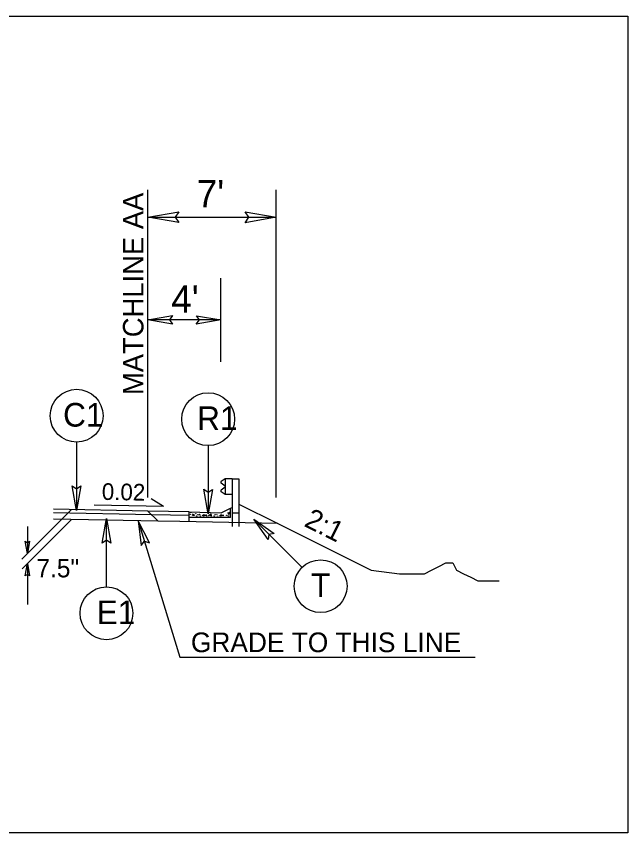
# Model space of a CAD drawing. Extents: x 1818040 to 1825768, y 638918 to 648046.
# Drawn here: x 1819386 to 1819887, y 645663 to 646332 of the extents above; entities that cross this region are included whole.
import ezdxf

# ---------------------------------------------------------------- set-up
doc = ezdxf.new("R2010")
doc.units = 0
for name, color, linetype in [('Default', 7, 'Continuous'), ('Old_Level_1', 7, 'Continuous'), ('Prop Dimension', 7, 'Continuous'), ('Prop Dimension Text', 7, 'Continuous'), ('Typical Curb CELL', 7, 'Continuous'), ('Typical Guardrail CELL', 7, 'Continuous'), ('Typical ID Circle CELL', 7, 'Continuous'), ('Typical Pavement Slope CELL', 7, 'Continuous'), ('Typical Pavement Slope Information CELL', 7, 'Continuous'), ('Typical Slope Point Local CELL', 7, 'Continuous'), ('Typical Terminator CELL', 7, 'Continuous'), ('Typical Text General CELL', 7, 'Continuous'), ('Typical Text ID Circle CELL', 7, 'Continuous'), ('Typical Text Label CELL', 7, 'Continuous')]:
    doc.layers.add(name, color=color, linetype=linetype)

msp = doc.modelspace()

# ---------------------------------------------------------------- linework, layer by layer
at = {"layer": 'Default'}
msp.add_lwpolyline([(1819299.94, 646331.55), (1819887.35, 646331.55), (1819887.35, 645662.6), (1819299.94, 645662.6)], close=True, dxfattribs=at)
at = {"layer": 'Old_Level_1'}
for p, q in [((1819431.63, 645927.44), (1819390.82, 645886.62)), ((1819561.96, 645928.44), (1819563.21, 645929.06)), ((1819497.41, 645922.99), (1819416.88, 645924.6)), ((1819494.22, 645926.18), (1819502.52, 645917.89)), ((1819527.98, 645922.38), (1819497.41, 645922.99)), ((1819527.98, 645917.38), (1819527.98, 645920.82)), ((1819431.63, 645919.31), (1819391.03, 645878.71)), ((1819395.41, 645913.58), (1819395.41, 645891.34)), ((1819502.52, 645917.89), (1819416.78, 645919.61)), ((1819486.3, 645918.22), (1819520.49, 645806.4)), ((1819520.25, 645917.54), (1819502.52, 645917.89)), ((1819600.67, 645915.93), (1819520.25, 645917.54)), ((1819395.41, 645883.08), (1819395.41, 645849.61)), ((1819520.49, 645806.4), (1819762.37, 645806.4))]:
    msp.add_line(p, q, dxfattribs=at)
at = {"layer": 'Prop Dimension'}
for p, q in [((1819494.22, 645937.39), (1819494.22, 646189.36)), ((1819599.22, 645937.39), (1819599.22, 646189.36)), ((1819494.22, 646166.86), (1819599.22, 646166.86)), ((1819553.98, 646048.36), (1819553.98, 646117.09)), ((1819553.98, 646082.73), (1819494.22, 646082.73))]:
    msp.add_line(p, q, dxfattribs=at)
at = {"layer": 'Typical Curb CELL'}
for p, q in [((1819554.22, 645924.57), (1819561.96, 645928.44)), ((1819561.96, 645920.82), (1819561.96, 645928.44)), ((1819527.98, 645925.51), (1819527.98, 645925.51)), ((1819527.98, 645920.82), (1819527.98, 645925.39)), ((1819561.96, 645920.82), (1819527.98, 645920.82)), ((1819528.1, 645925.5), (1819554.22, 645924.57)), ((1819530.65, 645922.53), (1819531.62, 645923.88)), ((1819532.01, 645922.6), (1819530.65, 645922.53)), ((1819531.62, 645923.88), (1819532.01, 645922.6)), ((1819539.26, 645921.96), (1819539.97, 645923.24)), ((1819541.13, 645922.4), (1819539.26, 645921.96)), ((1819539.97, 645923.24), (1819541.13, 645922.4)), ((1819544.71, 645922.53), (1819545.67, 645923.88)), ((1819546.06, 645922.6), (1819544.71, 645922.53)), ((1819545.67, 645923.88), (1819546.06, 645922.6)), ((1819553.31, 645921.96), (1819554.01, 645923.24)), ((1819555.17, 645922.4), (1819553.31, 645921.96)), ((1819554.01, 645923.24), (1819555.17, 645922.4)), ((1819559.81, 645924.69), (1819560, 645923.67)), ((1819561.55, 645924.18), (1819559.81, 645924.69)), ((1819560, 645923.67), (1819561.55, 645924.18))]:
    msp.add_line(p, q, dxfattribs=at)
for centre in [(1819528.99, 645923.51), (1819529.42, 645924.92), (1819533.55, 645924.08), (1819534.22, 645922.07), (1819534.85, 645921.69), (1819535.22, 645923.11), (1819536.07, 645923.09), (1819536.63, 645923.43), (1819537.16, 645922.13), (1819539.34, 645922.57), (1819541.65, 645922.39), (1819541.85, 645922.96), (1819541.96, 645923.63), (1819542.6, 645922.02), (1819543.68, 645922.53), (1819544.74, 645922.64), (1819546.09, 645922.07), (1819548.27, 645922.07), (1819548.9, 645921.69), (1819549.27, 645923.11), (1819550.68, 645923.43), (1819551.21, 645922.13), (1819553.39, 645922.57), (1819553.72, 645921.43), (1819555.71, 645922.39), (1819555.9, 645922.96), (1819558.79, 645922.64), (1819560.14, 645922.07), (1819561.23, 645925.14)]:
    msp.add_circle(centre, 0.0902, dxfattribs=at)
msp.add_arc((1819528.1, 645925.39), 0.117, 87.95199, 180, dxfattribs=at)
at = {"layer": 'Typical Guardrail CELL'}
for p, q in [((1819557.61, 645952.68), (1819554.36, 645950.4)), ((1819557.61, 645946.68), (1819554.36, 645948.96)), ((1819563.21, 645952.68), (1819557.61, 645952.68)), ((1819557.61, 645952.68), (1819557.61, 645939.63)), ((1819563.21, 645952.68), (1819563.21, 645924.72)), ((1819563.21, 645952.68), (1819568.8, 645952.68)), ((1819568.8, 645952.68), (1819568.8, 645924.72)), ((1819557.61, 645945.63), (1819554.36, 645943.35)), ((1819557.61, 645939.63), (1819554.36, 645941.92)), ((1819557.61, 645946.16), (1819557.61, 645946.68)), ((1819557.61, 645946.16), (1819557.61, 645945.63)), ((1819563.21, 645939.63), (1819557.61, 645939.63)), ((1819563.21, 645924.72), (1819568.8, 645924.72)), ((1819563.21, 645924.72), (1819563.21, 645913.37)), ((1819568.8, 645924.72), (1819568.8, 645913.37))]:
    msp.add_line(p, q, dxfattribs=at)
for centre, start, end in [((1819554.85, 645949.68), 125.00297, 235.0112), ((1819554.85, 645942.63), 125.0059, 235.0366)]:
    msp.add_arc(centre, 0.874, start, end, dxfattribs=at)
at = {"layer": 'Typical ID Circle CELL'}
for p, q in [((1819435.82, 645982.63), (1819435.82, 645926.71)), ((1819543.59, 645979.84), (1819543.59, 645923.91)), ((1819460.24, 645864.02), (1819460.24, 645919.95)), ((1819620.49, 645879.86), (1819580.93, 645919.39))]:
    msp.add_line(p, q, dxfattribs=at)
for centre in [(1819435.82, 646004.27), (1819543.59, 646001.47), (1819635.77, 645864.55), (1819460.24, 645842.39)]:
    msp.add_circle(centre, 21.64, dxfattribs=at)
at = {"layer": 'Typical Pavement Slope CELL'}
for p, q in [((1819494.22, 645926.18), (1819416.94, 645927.73)), ((1819527.98, 645925.51), (1819494.22, 645926.18))]:
    msp.add_line(p, q, dxfattribs=at)
at = {"layer": 'Typical Pavement Slope Information CELL'}
for q in [(1819496.9, 645936.03), (1819450.07, 645931.05)]:
    msp.add_line((1819507.03, 645929.91), q, dxfattribs=at)
at = {"layer": 'Typical Slope Point Local CELL'}
for p, q in [((1819568.8, 645931.86), (1819600.67, 645915.93)), ((1819600.67, 645915.93), (1819677.03, 645877.74))]:
    msp.add_line(p, q, dxfattribs=at)
msp.add_lwpolyline([(1819677.03, 645877.74), (1819700.37, 645874.84), (1819706.21, 645874.84), (1819714.97, 645874.84), (1819720.81, 645874.84), (1819726.64, 645877.74), (1819732.48, 645880.67), (1819738.31, 645883.6), (1819744.15, 645883.6), (1819747.08, 645877.74), (1819752.91, 645874.84), (1819758.75, 645871.91), (1819764.58, 645869), (1819770.42, 645869), (1819776.25, 645869), (1819782.09, 645869)], dxfattribs=at)
at = {"layer": 'Typical Terminator CELL'}
for points in [[(1819519.54, 646162.5), (1819494.22, 646166.86), (1819519.68, 646171.36), (1819516.44, 646166.86)], [(1819573.91, 646171.22), (1819599.22, 646166.86), (1819573.77, 646162.36), (1819577.01, 646166.86)], [(1819514.26, 646079.28), (1819494.22, 646082.73), (1819514.37, 646086.29), (1819511.81, 646082.73)], [(1819533.95, 646086.18), (1819553.98, 646082.73), (1819533.83, 646079.16), (1819536.39, 646082.73)], [(1819439.27, 645946.75), (1819435.82, 645926.71), (1819432.26, 645946.86), (1819435.82, 645944.3)], [(1819547.04, 645943.95), (1819543.59, 645923.91), (1819540.03, 645944.06), (1819543.59, 645941.5)], [(1819456.79, 645899.91), (1819460.24, 645919.95), (1819463.8, 645899.8), (1819460.24, 645902.36)], [(1819495.38, 645900.01), (1819486.29, 645918.19), (1819488.7, 645897.87), (1819491.37, 645901.35)], [(1819592.66, 645902.79), (1819580.93, 645919.39), (1819597.7, 645907.67), (1819593.37, 645906.96)], [(1819397.21, 645901.34), (1819395.41, 645891.34), (1819393.71, 645901.42), (1819395.48, 645900.13)], [(1819393.72, 645873.06), (1819395.41, 645883.08), (1819397.23, 645873.02), (1819395.44, 645874.29)]]:
    msp.add_lwpolyline(points, close=True, dxfattribs=at)

# ---------------------------------------------------------------- texts
at = {"layer": 'Prop Dimension Text'}
for s, height, p in [("7'", 22.5, (1819534.26, 646174.93)), ("4'", 22.5, (1819513.37, 646088.66)), ('7.5"', 15, (1819402.85, 645871.83))]:
    msp.add_text(s, height=height, dxfattribs=at).set_placement(p)
at = {"layer": 'Typical Pavement Slope Information CELL'}
msp.add_text('0.02 ', height=13.66, rotation=358.85426, dxfattribs=at).set_placement((1819456.32, 645935.35))
at = {"layer": 'Typical Text General CELL'}
msp.add_text('GRADE TO THIS LINE', height=16.113, dxfattribs=at).set_placement((1819529.47, 645810.52))
at = {"layer": 'Typical Text ID Circle CELL'}
for s, height, p in [('C1', 19.368, (1819424.71, 645995.35)), ('R1', 19.368, (1819534.52, 645992.55)), ('T', 19.37, (1819627.86, 645855.64)), ('E1', 19.368, (1819452.25, 645833.48))]:
    msp.add_text(s, height=height, dxfattribs=at).set_placement(p)
at = {"layer": 'Typical Text Label CELL'}
for s, height, rotation, p in [('MATCHLINE AA', 16.7844, 90, (1819490.56, 646021.21)), ('2:1', 16.784, 333.43495, (1819621.37, 645914.11))]:
    msp.add_text(s, height=height, rotation=rotation, dxfattribs=at).set_placement(p)

doc.saveas('drawing.dxf')
